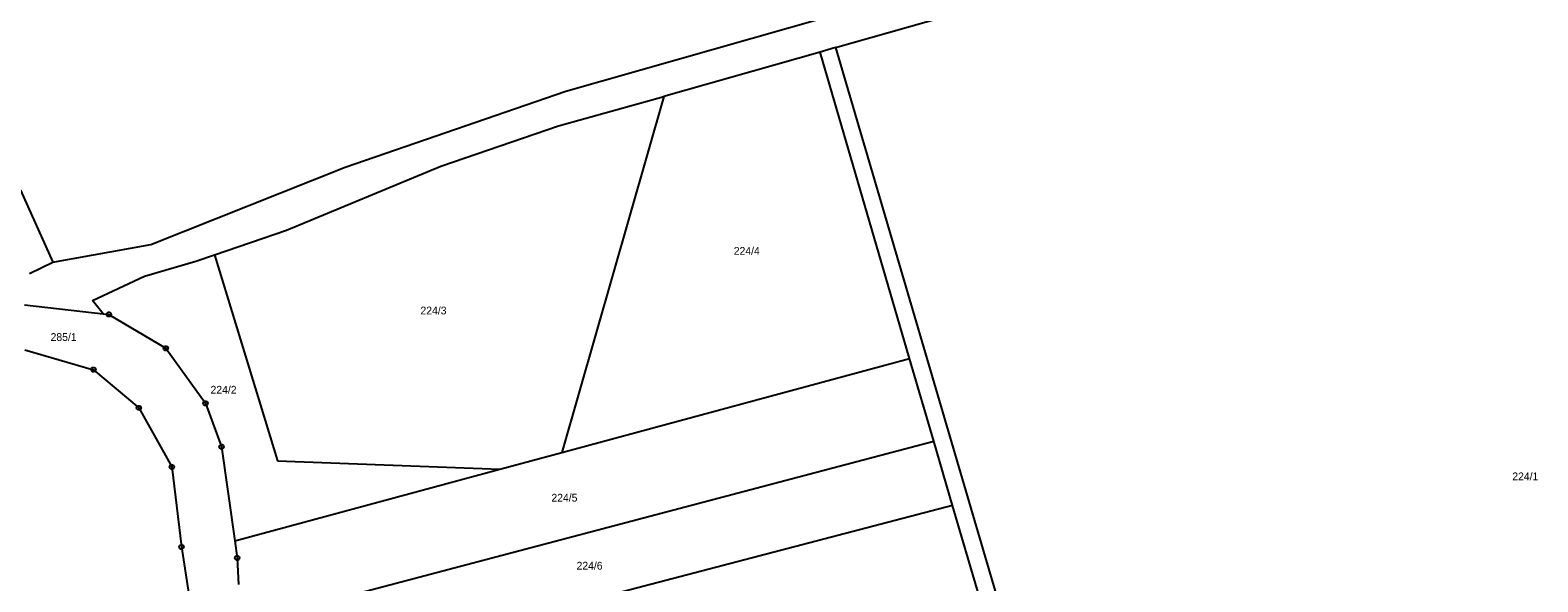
# Model space of a CAD drawing. Extents: x -779723 to -777378, y -1011169 to -1009297.
# Drawn here: x -778986.4 to -778657, y -1010240.1 to -1010119.6 of the extents above; entities that cross this region are included whole.
import ezdxf

# ---------------------------------------------------------------- set-up
doc = ezdxf.new("R2010")
doc.units = 0
for name, color, linetype in [('Default', 7, 'Continuous'), ('KN_HRANICE', 7, 'Continuous'), ('KN_PARCELY', 7, 'Continuous')]:
    doc.layers.add(name, color=color, linetype=linetype)

# ---------------------------------------------------------------- blocks, each defined once
blk = doc.blocks.new('105')
at = {"layer": 'Default'}
blk.add_line((-0.12, 0), (0.12, 0), dxfattribs=at)
blk.add_lwpolyline([(0.15, 0.48), (0.4, 0.3), (0.5, 0.01), (0.4, -0.28), (0.15, -0.46), (-0.16, -0.46), (-0.41, -0.28), (-0.51, 0.01), (-0.41, 0.3), (-0.16, 0.48), (0.15, 0.48)], dxfattribs=at)

msp = doc.modelspace()

# ---------------------------------------------------------------- linework, layer by layer
at = {"layer": 'KN_HRANICE'}
for p, q in [((-778869.36, -1010132.88), (-778766.08, -1010103.5)), ((-778810.44, -1010123.41), (-778782.95, -1010115.6)), ((-778810.44, -1010123.41), (-778813.85, -1010124.38)), ((-778810.44, -1010123.41), (-778760.75, -1010292.49)), ((-778813.85, -1010124.38), (-778847.96, -1010134.1)), ((-778794.28, -1010191.27), (-778813.85, -1010124.38)), ((-778917.58, -1010149.52), (-778869.36, -1010132.88)), ((-778870.96, -1010140.49), (-778847.96, -1010134.1)), ((-778847.96, -1010134.1), (-778870.23, -1010211.82)), ((-778896.72, -1010149.28), (-778870.96, -1010140.49)), ((-778960.05, -1010166.44), (-778917.58, -1010149.52)), ((-778930.42, -1010163.26), (-778896.72, -1010149.28)), ((-778988.54, -1010154.56), (-778981.44, -1010170.24)), ((-778981.44, -1010170.24), (-778960.05, -1010166.44)), ((-778946.12, -1010168.67), (-778930.42, -1010163.26)), ((-778950.22, -1010170.08), (-778946.12, -1010168.67)), ((-778946.12, -1010168.67), (-778932.35, -1010213.67)), ((-778986.55, -1010172.74), (-778981.44, -1010170.24)), ((-778961.42, -1010173.29), (-778950.22, -1010170.08)), ((-778972.81, -1010178.62), (-778961.42, -1010173.29)), ((-778987.62, -1010179.6), (-778970.48, -1010181.53)), ((-778970.48, -1010181.53), (-778972.81, -1010178.62)), ((-778970.48, -1010181.53), (-778969.19, -1010181.68)), ((-778969.19, -1010181.68), (-778956.78, -1010189.07)), ((-778987.54, -1010189.4), (-778972.6, -1010193.75)), ((-778956.78, -1010189.07), (-778948.1, -1010201.08)), ((-778870.23, -1010211.82), (-778794.28, -1010191.27)), ((-778789, -1010209.36), (-778794.28, -1010191.27)), ((-778972.6, -1010193.75), (-778962.68, -1010202.09)), ((-778962.68, -1010202.09), (-778955.45, -1010215)), ((-778948.1, -1010201.08), (-778944.59, -1010210.6)), ((-778944.59, -1010210.6), (-778941.69, -1010231.16)), ((-778939.44, -1010249.05), (-778789, -1010209.36)), ((-778883.82, -1010215.5), (-778870.23, -1010211.82)), ((-778784.9, -1010223.38), (-778789, -1010209.36)), ((-778955.45, -1010215), (-778953.35, -1010232.46)), ((-778941.69, -1010231.16), (-778883.82, -1010215.5)), ((-778932.35, -1010213.67), (-778883.82, -1010215.5)), ((-778784.9, -1010223.38), (-778936.98, -1010263.15)), ((-778779.19, -1010242.93), (-778784.9, -1010223.38)), ((-778941.69, -1010231.16), (-778941.17, -1010234.88)), ((-778953.35, -1010232.46), (-778950.34, -1010251.89)), ((-778941.17, -1010234.88), (-778940.9, -1010240.67))]:
    msp.add_line(p, q, dxfattribs=at)

# ---------------------------------------------------------------- block references
at = {"layer": 'KN_PARCELY'}
for p in [(-778969.19, -1010181.68), (-778956.78, -1010189.07), (-778972.6, -1010193.75), (-778962.68, -1010202.09), (-778948.1, -1010201.08), (-778944.59, -1010210.6), (-778955.45, -1010215), (-778953.35, -1010232.46), (-778941.17, -1010234.88)]:
    msp.add_blockref('105', p, dxfattribs=at)

# ---------------------------------------------------------------- texts
for s, p in [('224/4', (-778832.7, -1010168.66)), ('224/3', (-778901.14, -1010181.67)), ('285/1', (-778981.95, -1010187.47)), ('224/2', (-778947.01, -1010198.98)), ('224/1', (-778662.62, -1010217.9)), ('224/5', (-778872.54, -1010222.56)), ('224/6', (-778867.04, -1010237.41))]:
    msp.add_text(s, height=1.7, dxfattribs=at).set_placement(p)

doc.saveas('drawing.dxf')
